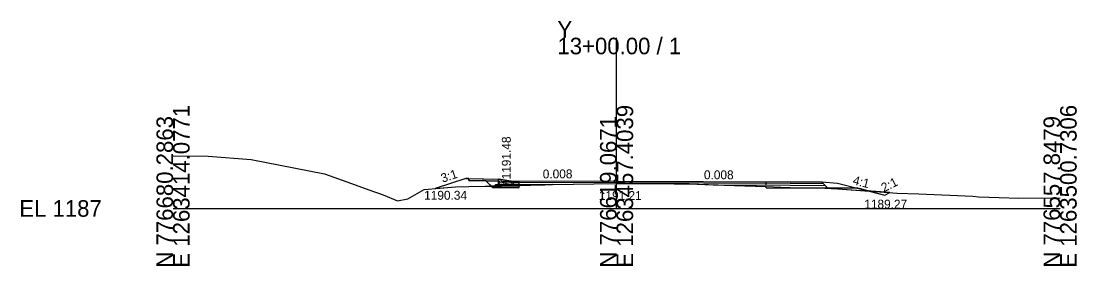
# Model space of a CAD drawing. Extents: x -51 to 1263719, y -10 to 776845.
# Drawn here: x -25.7 to 152.8, y 2990.3 to 3031.6 of the extents above; entities that cross this region are included whole.
import ezdxf

# ---------------------------------------------------------------- set-up
doc = ezdxf.new("R2010")
doc.units = 0
for name, color, linetype in [('Exist Cross Section Cell', 7, 'Continuous'), ('Exist XS Center Line Elevation Label', 7, 'Continuous'), ('Exist XS Ground Line', 7, 'Continuous'), ('Prop CMT Pvmt Course 1', 7, 'Continuous'), ('Prop CMT Pvmt Course 4', 7, 'Continuous'), ('Prop CMT Shld Paved Course 1', 7, 'Continuous'), ('Prop CMT Shld Paved Course 2', 7, 'Continuous'), ('Prop CMT Shld Paved Course 4', 7, 'Continuous'), ('Prop CMT Subgrade Earthwork', 7, 'Continuous'), ('Prop Conc 4in Sidewalk', 7, 'Continuous'), ('Prop XS Ditch Standard Text', 7, 'Continuous'), ('Prop XS Earthwork Shape', 7, 'Continuous'), ('Prop XS Elevation Labels', 7, 'Continuous'), ('Prop XS Finish Grade', 7, 'Continuous'), ('Prop XS SE Text', 7, 'Continuous'), ('Prop XS Side Slope Text', 7, 'Continuous'), ('Scratch_Level_0', 7, 'Continuous'), ('Typical Curb CELL', 7, 'Continuous')]:
    doc.layers.add(name, color=color, linetype=linetype)

msp = doc.modelspace()

# ---------------------------------------------------------------- linework, layer by layer
at = {"layer": 'Exist Cross Section Cell'}
for p, q in [((75, 3000), (75, 3028.83)), ((0, 3000), (75, 3000)), ((75, 3000), (150, 3000))]:
    msp.add_line(p, q, dxfattribs=at)
at = {"layer": 'Exist XS Ground Line'}
msp.add_lwpolyline([(0, 3008.88), (5.93, 3008.8), (13.2, 3008.25), (25.61, 3005.87), (30.17, 3004.22), (33.12, 3003.16), (35.53, 3002.29), (37.98, 3001.3), (39.68, 3001.62), (42.48, 3003.19), (47.78, 3003.64), (50.04, 3003.71), (58.28, 3003.9), (58.71, 3003.89), (62.23, 3003.97), (62.6, 3003.98), (64.15, 3004.03), (71.18, 3004.15), (75.18, 3004.22), (76.76, 3004.23), (78.81, 3004.24), (79.18, 3004.24), (84.73, 3004.18), (86.14, 3004.17), (87.3, 3004.14), (100.31, 3003.73), (104.01, 3003.52), (104.55, 3003.48), (105.24, 3003.48), (109.57, 3003.48), (112.35, 3003.31), (118.05, 3002.91), (122.46, 3002.59), (126.12, 3002.48), (135.24, 3002.07), (136.22, 3001.96), (139.67, 3001.85), (143, 3001.75), (150, 3001.8)], dxfattribs=at)
at = {"layer": 'Prop CMT Pvmt Course 1'}
for p, q in [((57.51, 3004.55), (57.51, 3004.3)), ((58.51, 3004.31), (57.51, 3004.3)), ((58.51, 3004.31), (58.51, 3004.56))]:
    msp.add_line(p, q, dxfattribs=at)
at = {"layer": 'Prop CMT Pvmt Course 4'}
for p, q in [((54.51, 3003.97), (54.05, 3003.51)), ((57.51, 3003.51), (54.05, 3003.51)), ((57.51, 3003.97), (54.51, 3003.97)), ((58.5, 3003.52), (57.5, 3003.51)), ((58.51, 3003.52), (58.51, 3003.97))]:
    msp.add_line(p, q, dxfattribs=at)
at = {"layer": 'Prop CMT Shld Paved Course 1'}
for p, q in [((75, 3004.37), (58.51, 3004.31)), ((75, 3004.37), (104.38, 3004.26)), ((100.29, 3004.27), (100.29, 3004.52)), ((104.38, 3004.26), (109.94, 3004.23)), ((109.94, 3004.23), (109.69, 3004.49))]:
    msp.add_line(p, q, dxfattribs=at)
at = {"layer": 'Prop CMT Shld Paved Course 2'}
for p, q in [((58.51, 3003.97), (57.5, 3003.97)), ((57.51, 3003.97), (57.51, 3004.3)), ((58.51, 3003.97), (58.51, 3004.31)), ((62.88, 3003.99), (58.51, 3003.97)), ((64.36, 3004.04), (71.18, 3004.15)), ((71.18, 3004.15), (75.18, 3004.22)), ((75.18, 3004.22), (76.76, 3004.23)), ((78.81, 3004.24), (76.76, 3004.23)), ((79.18, 3004.24), (78.81, 3004.24)), ((79.18, 3004.24), (84.73, 3004.18)), ((84.73, 3004.18), (86.14, 3004.17)), ((87.3, 3004.14), (86.14, 3004.17)), ((87.3, 3004.14), (91.32, 3004.01)), ((92.73, 3003.97), (104.38, 3003.92)), ((100.29, 3003.94), (100.29, 3004.27)), ((104.38, 3003.92), (110.28, 3003.9)), ((110.28, 3003.9), (109.94, 3004.23))]:
    msp.add_line(p, q, dxfattribs=at)
at = {"layer": 'Prop CMT Shld Paved Course 4'}
for p, q in [((58.28, 3003.9), (57.51, 3003.88)), ((58.71, 3003.89), (58.28, 3003.9)), ((58.71, 3003.89), (62.23, 3003.97)), ((62.6, 3003.98), (62.23, 3003.97)), ((64.15, 3004.03), (62.6, 3003.98)), ((91.32, 3004.01), (100.31, 3003.73)), ((100.31, 3003.73), (104.01, 3003.52)), ((104.38, 3003.49), (104.01, 3003.52)), ((104.38, 3003.46), (115.78, 3003.42)), ((110.28, 3003.9), (110.74, 3003.44))]:
    msp.add_line(p, q, dxfattribs=at)
at = {"layer": 'Prop CMT Subgrade Earthwork'}
for p, q in [((54.05, 3003.51), (52.88, 3004.68)), ((57.51, 3003.51), (54.05, 3003.51)), ((57.5, 3003.51), (58.51, 3003.52)), ((58.51, 3003.52), (58.51, 3003.89)), ((100.31, 3003.48), (100.31, 3003.73)), ((100.31, 3003.48), (115.78, 3003.42))]:
    msp.add_line(p, q, dxfattribs=at)
at = {"layer": 'Prop Conc 4in Sidewalk'}
for p, q in [((50.01, 3005.07), (55.01, 3004.97)), ((50.01, 3005.07), (50.01, 3004.74)), ((50.01, 3004.74), (55.01, 3004.64)), ((55.01, 3004.64), (55.01, 3004.97))]:
    msp.add_line(p, q, dxfattribs=at)
at = {"layer": 'Prop XS Earthwork Shape'}
for points in [[(44.31, 3003.35), (47.78, 3003.64), (50.04, 3003.71), (53.77, 3003.79), (52.88, 3004.68), (50.01, 3004.74), (50.01, 3005.07), (49.51, 3005.08)], [(58.51, 3003.89), (58.28, 3003.9), (57.51, 3003.88), (53.77, 3003.79), (52.88, 3004.68), (55.01, 3004.64), (55.01, 3004.97), (57.51, 3004.55), (57.51, 3004.3), (57.51, 3003.97), (58.51, 3003.97), (62.88, 3003.99), (62.6, 3003.98), (62.23, 3003.97), (58.71, 3003.89)], [(58.51, 3003.89), (58.28, 3003.9), (57.51, 3003.88), (53.77, 3003.79), (54.05, 3003.51), (57.51, 3003.51), (58.51, 3003.52)], [(104.38, 3003.49), (104.55, 3003.48), (105.24, 3003.48), (109.57, 3003.48), (110.19, 3003.44), (104.38, 3003.46)], [(110.19, 3003.44), (112.35, 3003.31), (117.75, 3002.93), (115.78, 3003.42), (110.74, 3003.44)], [(117.75, 3002.93), (120.38, 3002.27), (121.2, 3002.68), (118.05, 3002.91)]]:
    msp.add_lwpolyline(points, close=True, dxfattribs=at)
at = {"layer": 'Prop XS Finish Grade'}
for p, q in [((49.51, 3005.08), (44.31, 3003.35)), ((49.51, 3005.08), (55.01, 3004.97)), ((58.51, 3004.56), (57.51, 3004.55)), ((75, 3004.62), (58.51, 3004.56)), ((75, 3004.62), (104.38, 3004.51)), ((104.38, 3004.51), (109.69, 3004.49)), ((109.69, 3004.49), (112.38, 3004.27)), ((112.38, 3004.27), (120.38, 3002.27)), ((120.38, 3002.27), (121.2, 3002.68))]:
    msp.add_line(p, q, dxfattribs=at)
at = {"layer": 'Scratch_Level_0'}
msp.add_line((57.51, 3004.55), (55.01, 3004.97), dxfattribs=at)
at = {"layer": 'Typical Curb CELL'}
for p, q in [((55.01, 3003.97), (55.01, 3004.97)), ((55.01, 3004.97), (55.27, 3004.97)), ((55.51, 3004.72), (55.51, 3004.73)), ((55.01, 3003.97), (57.51, 3003.97)), ((55.04, 3004.59), (55.2, 3004.64)), ((55.18, 3004.55), (55.04, 3004.59)), ((55.17, 3004.27), (55.07, 3004.2)), ((55.07, 3004.2), (55.23, 3004.16)), ((55.23, 3004.16), (55.17, 3004.27)), ((55.2, 3004.64), (55.18, 3004.55)), ((57.51, 3004.55), (55.76, 3004.48)), ((55.91, 3004.33), (55.88, 3004.22)), ((55.88, 3004.22), (56, 3004.21)), ((56, 3004.21), (55.91, 3004.33)), ((56.42, 3004.27), (56.32, 3004.2)), ((56.32, 3004.2), (56.48, 3004.16)), ((56.48, 3004.16), (56.42, 3004.27)), ((57.16, 3004.33), (57.13, 3004.22)), ((57.13, 3004.22), (57.25, 3004.21)), ((57.25, 3004.21), (57.16, 3004.33)), ((57.51, 3003.97), (57.51, 3004.55))]:
    msp.add_line(p, q, dxfattribs=at)
for centre in [(55.02, 3004.86), (55.24, 3004.89), (55.07, 3004.68), (55.15, 3004.02), (55.17, 3004.4), (55.29, 3004.46), (55.32, 3004.06), (55.47, 3004.29), (55.5, 3003.99), (55.55, 3004.48), (55.56, 3004.11), (55.56, 3004.43), (55.59, 3004.26), (55.67, 3004.02), (55.74, 3004.35), (55.77, 3004.45), (55.88, 3004.05), (55.96, 3004.41), (56.04, 3003.98), (56.06, 3004.46), (56.09, 3004.21), (56.17, 3004.37), (56.19, 3004.16), (56.23, 3004.4), (56.24, 3004.31), (56.25, 3004), (56.4, 3004.02), (56.42, 3004.4), (56.54, 3004.46), (56.57, 3004.06), (56.72, 3004.29), (56.75, 3003.99), (56.8, 3004.48), (56.81, 3004.11), (56.81, 3004.43), (56.84, 3004.26), (56.92, 3004.02), (56.99, 3004.35), (57.02, 3004.45), (57.13, 3004.05), (57.17, 3004.51), (57.21, 3004.41), (57.29, 3003.98), (57.31, 3004.5), (57.34, 3004.21), (57.42, 3004.37), (57.43, 3004.16), (57.47, 3004.4), (57.49, 3004.31), (57.5, 3004)]:
    msp.add_circle(centre, 0.00802, dxfattribs=at)
for centre, start, end in [((55.27, 3004.73), 0, 90), ((55.75, 3004.72), 180, 272.3845)]:
    msp.add_arc(centre, 0.24, start, end, dxfattribs=at)

# ---------------------------------------------------------------- texts
at = {"layer": 'Exist Cross Section Cell'}
for s, p in [('Y', (65, 3028.83)), ('13+00.00 / 1', (65, 3026.03)), ('EL 1187', (-26, 2998.6))]:
    msp.add_text(s, height=2.8, dxfattribs=at).set_placement(p)
for s, p in [('E 1263414.0771', (2.8, 2990)), ('E 1263457.4039', (77.8, 2990)), ('E 1263500.7306', (152.8, 2990)), ('N 776680.2863', (0, 2990)), ('N 776619.0671', (75, 2990)), ('N 776557.8479', (150, 2990))]:
    msp.add_text(s, height=2.8, rotation=90, dxfattribs=at).set_placement(p)
at = {"layer": 'Exist XS Center Line Elevation Label'}
msp.add_text('1191.21', height=1.5, dxfattribs=at).set_placement((72, 3001.43))
at = {"layer": 'Prop XS Ditch Standard Text'}
for s, p in [('1190.34', (42.46, 3001.47)), ('1189.27', (116.89, 2999.98))]:
    msp.add_text(s, height=1.5, dxfattribs=at).set_placement(p)
at = {"layer": 'Prop XS Elevation Labels'}
msp.add_text('1191.48', height=1.5, rotation=90, dxfattribs=at).set_placement((57.11, 3004.9))
at = {"layer": 'Prop XS SE Text'}
for rotation, p in [(0.2292, (62.52, 3005.07)), (359.7708, (89.77, 3004.94))]:
    msp.add_text('0.008', height=1.5, rotation=rotation, dxfattribs=at).set_placement(p)
at = {"layer": 'Prop XS Side Slope Text'}
for s, rotation, p in [('3:1', 18.4349, (45.58, 3004.33)), ('4:1', 345.9638, (114.84, 3004.09)), ('2:1', 26.5651, (120.21, 3002.72))]:
    msp.add_text(s, height=1.5, rotation=rotation, dxfattribs=at).set_placement(p)

doc.saveas('drawing.dxf')
